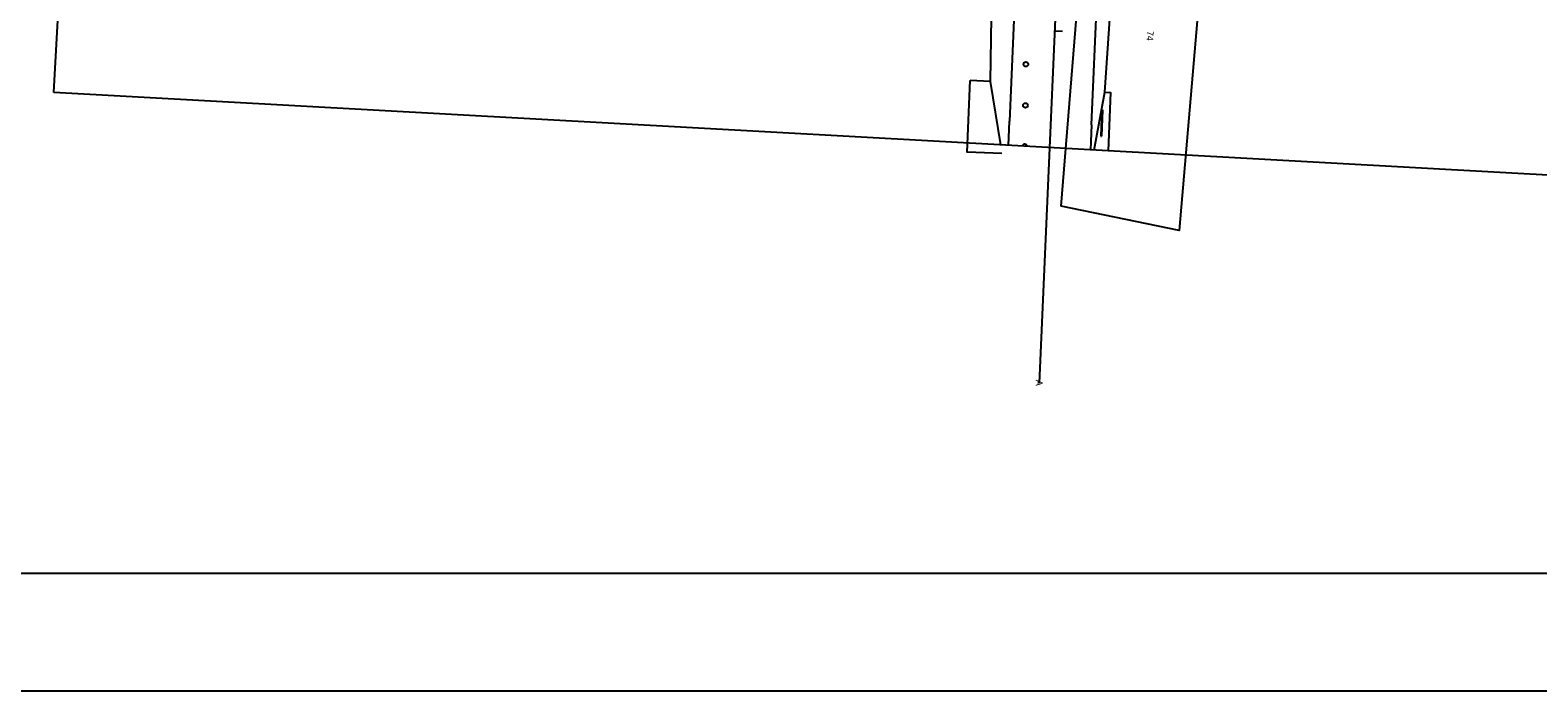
# Model space of a CAD drawing. Extents: x 679444 to 687671, y 733868 to 736107.
# Drawn here: x 685370 to 686654, y 733868 to 734431 of the extents above; entities that cross this region are included whole.
import ezdxf

# ---------------------------------------------------------------- set-up
doc = ezdxf.new("R2010")
doc.units = 0
for name, color, linetype in [('$', 7, 'Continuous'), ('border All Plan 20-40 - Level 1', 7, 'Continuous'), ('C-TOPO', 7, 'Continuous'), ('C-TOPO-FEAT', 7, 'Continuous'), ('Clipping Boundary', 7, 'Continuous'), ('MOT Stage 1', 7, 'Continuous'), ('R_Horz Alg', 7, 'Continuous'), ('R_Horz Alg Station', 7, 'Continuous'), ('R_TYPE_A_CURB', 7, 'Continuous'), ('RW-EX', 7, 'Continuous'), ('RW-PR', 7, 'Continuous'), ('V-NODE', 7, 'Continuous')]:
    doc.layers.add(name, color=color, linetype=linetype)

# ---------------------------------------------------------------- blocks, each defined once
blk = doc.blocks.new('BAREL_1872')
at = {"layer": 'MOT Stage 1'}
blk.add_circle((0, 0), 2.88, dxfattribs=at)
blk = doc.blocks.new('BAREL_1873')
at = {"layer": 'MOT Stage 1'}
blk.add_circle((0, 0), 2.88, dxfattribs=at)

msp = doc.modelspace()

# ---------------------------------------------------------------- linework, layer by layer
at = {"layer": '$'}
msp.add_lwpolyline([(679553.9, 733968.3), (687571.1, 733968.3), (687571.1, 736006.7), (679553.9, 736006.7), (679553.9, 733968.3)], dxfattribs=at)
at = {"layer": 'border All Plan 20-40 - Level 1'}
for p, q in [((685390, 734377.6), (685446.8, 735403.4)), ((686968.5, 734290.2), (685390, 734377.6))]:
    msp.add_line(p, q, dxfattribs=at)
at = {"layer": 'C-TOPO'}
msp.add_lwpolyline([(679453.9, 733868.3), (687671.1, 733868.3), (687671.1, 736106.7), (679453.9, 736106.7), (679453.9, 733868.3)], dxfattribs=at)
at = {"layer": 'C-TOPO-FEAT'}
msp.add_lwpolyline([(679553.9, 733968.3), (687571.1, 733968.3), (687571.1, 736006.7), (679553.9, 736006.7), (679553.9, 733968.3)], dxfattribs=at)
at = {"layer": 'Clipping Boundary'}
msp.add_lwpolyline([(686247.9, 734280.9), (686271.4, 734571.4), (686288.3, 734779.8), (686336.9, 734815.2), (686664.2, 734806), (686835.8, 734801.2), (686820.4, 734729.1), (686388.1, 734723.2), (686348.1, 734260)], close=True, dxfattribs=at)
at = {"layer": 'MOT Stage 1'}
msp.add_arc((686216.7, 734331.6), 2, 4.1955, 169.4622, dxfattribs=at)
at = {"layer": 'R_Horz Alg Station'}
msp.add_line((686256.3, 734756.6), (686229.1, 734130.1), dxfattribs=at)
msp.add_lwpolyline([(686248.8, 734429.5), (686242.1, 734429.8)], dxfattribs=at)
at = {"layer": 'R_TYPE_A_CURB'}
for p, q in [((686282.5, 734362.8), (686281.6, 734340.3)), ((686283, 734362.8), (686282.1, 734340.3)), ((686282.5, 734362.8), (686283, 734362.8)), ((686281.6, 734340.3), (686282.1, 734340.3))]:
    msp.add_line(p, q, dxfattribs=at)
at = {"layer": 'RW-EX'}
for q in [(686287, 734655.9), (686272.7, 734328.7)]:
    msp.add_line((686273.7, 734350.1), q, dxfattribs=at)
for points in [[(686197.5, 734439.6), (686207.5, 734439.1), (686203.7, 734353.2)], [(686202.8, 734332.6), (686203.7, 734353.2)]]:
    msp.add_lwpolyline(points, dxfattribs=at)
at = {"layer": 'RW-PR'}
msp.add_line((686187.2, 734387.1), (686170.2, 734387.9), dxfattribs=at)
for points in [[(685416.5, 734855.9), (685615.3, 734844.5), (685918.8, 734822.8), (685992.9, 734807.5), (686092.7, 734800.3), (686145.5, 734791.5), (686191.4, 734759.5), (686200.2, 734731.9), (686188.4, 734460.2), (686187.2, 734387.1), (686196, 734333)], [(686275.9, 734328.5), (686284.9, 734377.9), (686298.6, 734577.5), (686317.9, 734676.7), (686320.1, 734726.7), (686331.2, 734751.2)], [(686197.2, 734325.6), (686167.6, 734326.9), (686170.2, 734387.9)], [(686284.9, 734377.9), (686289.9, 734377.6), (686287.7, 734327.9)]]:
    msp.add_lwpolyline(points, dxfattribs=at)
at = {"layer": 'V-NODE'}
msp.add_lwpolyline([(679553.9, 733968.3), (687571.1, 733968.3), (687571.1, 736006.7), (679553.9, 736006.7), (679553.9, 733968.3)], dxfattribs=at)

# ---------------------------------------------------------------- block references
at = {"layer": 'MOT Stage 1', "xscale": 0.6945420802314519, "yscale": 0.6945420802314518, "rotation": 87.04179557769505}
for name, p in [('BAREL_1873', (686217.7, 734401.6)), ('BAREL_1872', (686217.3, 734366.6))]:
    msp.add_blockref(name, p, dxfattribs=at)

# ---------------------------------------------------------------- texts
at = {"layer": '$'}
msp.add_text('74', height=5.6, rotation=267.5058, dxfattribs=at).set_placement((686320.9, 734430.1))
at = {"layer": 'R_Horz Alg'}
msp.add_text('A', height=6, rotation=267.5057, dxfattribs=at).set_placement((686226.2, 734133.2))

doc.saveas('drawing.dxf')
